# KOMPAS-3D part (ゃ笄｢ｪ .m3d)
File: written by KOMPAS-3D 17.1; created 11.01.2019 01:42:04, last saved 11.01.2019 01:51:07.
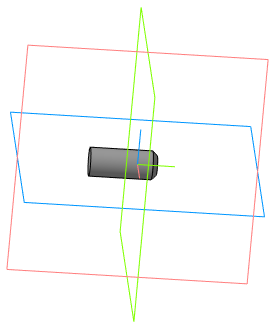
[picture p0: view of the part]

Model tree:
1. Эскиз:1
2. Элемент выдавливания:1
     Расстояние 1 = 4
3. Фаска:3
     Угол = 45; Длина 1 = 1; Длина 2 = 1
4. Элемент выдавливания:2
     Расстояние 1 = 10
